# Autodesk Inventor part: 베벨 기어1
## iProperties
Created: 2012-07
Part Number: 베벨 기어1
Material: Steel, Mild
Document SubType Name: Modeling
Designer: SeoGD™ [www.esajin.kr]
Categories: <?xml version="1.0" encoding="UTF-16"?> <MemberInstance><Categories><FamilyTemplate><FamilyTemplateParameter ValueType="xs:double" Id="1" ObjectReferenceKey="da
Mass: 60.9118 g
Surface Area: 34.3074 cm^2
Volume: 7.7496 cm^3
Density: 7.86 g/cm^3
CustomPartVersion: 1
Author: SeoGD™ [www.esajin.kr]
